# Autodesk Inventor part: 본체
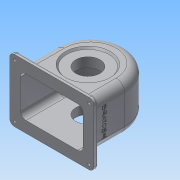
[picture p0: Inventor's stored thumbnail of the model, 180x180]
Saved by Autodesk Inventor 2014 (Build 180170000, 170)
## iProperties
Created: 2016-01
Part Number: 본체
Material: 알루미늄 6061
Document SubType Name: Modeling
Designer: user
Density: 2.71 g/cm^3
Appearance: 알루미늄 - 평지
Mass: 757.291 g
Surface Area: 1005.83 cm^2
Volume: 279.443 cm^3
Author: user
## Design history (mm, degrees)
sketch "스케치3"
  geometry: L1 (-57, -64)-(-57, 0); L2 (57, 0)-(57, -64); L3 (-57, -64)-(57, -64); A1 r 57 centre (0, 0) between (57, 0) and (-57, 0); 2 further points
  constraints: 6 end point, 3 point on circle, 2 tangent, 1 centre point, 1 coincident, 1 horizontal alignment, 1 parallel, 1 perpendicular, 1 vertical
  dimensions: "d6" = 64 distance of L1.start L1.end; "d7" = 121 vertical distance of L2.end point (0, 57)
extrude "돌출2" new body sketch "스케치3" distance "d8" = 77; taper "d9" = 0 deg
feature "쉘1" dims "d10" = 5
fillet "모깎기1" dims "d11" = 9
fillet "모깎기2" dims "d12" = 14
sketch "스케치4"
  geometry: L1 (100, 14)-(100, 63) reference; L2 (0, 77)-(86, 77) reference; L3 (-14, 14)-(-14, 63) reference; L4 (86, 0)-(0, 0) reference; L5 (-27, 90.5)-(113, 90.5); L6 (113, 90.5)-(113, -13.5); L7 (113, -13.5)-(-27, -13.5); L8 (-27, -13.5)-(-27, 90.5); A1 r 14 centre (86, 14) between (86, 0) and (100, 14) reference; A2 r 14 centre (86, 63) between (100, 63) and (86, 77) reference; A3 r 14 centre (0, 63) between (0, 77) and (-14, 63) reference; A4 r 14 centre (0, 14) between (-14, 14) and (0, 0) reference; 5 further points
  constraints: 8 end point, 4 midpoint, 2 parallel, 1 horizontal, 1 horizontal alignment, 1 perpendicular, 1 vertical alignment
  dimensions: "d13" = 104 distance of L7.end L5.start; "d14" = 140 distance of L5.start L5.end
extrude "돌출3" join sketch "스케치4" distance "d15" = 7; taper "d16" = 0 deg
sketch "스케치5"
  geometry: L1 (0, 63)-(0, 77) reference; L2 (0, 77)-(0, 77) reference; L3 (0, 63)-(0, 77) reference; L4 (0, 63)-(0, 63) reference; L5 (-57, 77)-(0, 77) reference; L6 (43, 72)-(0, 72) reference; L7 (35.747, 72)-(24, 58); L8 (24, 58)-(-4, 58); L9 (-4, 58)-(-4, 77); L10 (-64, -13.5)-(-64, 90.5) reference; L11 (0, 77)-(43, 77) reference; L12 (35.747, 72)-(-4, 72); 1 further point
  constraints: 8 end point, 2 parallel, 2 point on line, 1 horizontal alignment, 1 vertical
  dimensions: "d17" = 60 distance from line of L10 L9.end; "d18" = 50 deg angle of L8 L7; "d19" = 56 diameter of L7.end L9; "d20" = 19 distance between parallel lines of L8 L11
revolve "회전1" sketch "스케치5" stored, may be unused: angle "d21" = 90 deg
sketch "스케치6"
  geometry: L1 (0, 0)-(-57, 0) reference; L2 (-32, 58)-(24, 58) reference; L3 (43, 0)-(0, 0) reference; L4 (-4, -10)-(-4, 5); L5 (-64, -13.5)-(-64, 90.5) reference; L6 (-64, 5)-(0, 5) reference; L7 (-4, -10)-(27, -10); L8 (27, -10)-(27, 5); L9 (27, 5)-(-4, 5); 1 further point
  constraints: 8 end point, 2 parallel, 2 perpendicular, 1 horizontal alignment, 1 midpoint
  dimensions: "d69" = 60 distance between parallel lines of L5 L4; "d70" = 10 vertical distance of L3.start L4.start; "d71" = 62 diameter of L7.end L4
node "작업 평면2"
  node "작업 평면1"
sketch "스케치7"
  geometry: L1 (43, 0)-(-43, 0) reference; L2 (-57, 14)-(-57, 63) reference; C1 r 6 at (0, 38.5); 2 further points
  constraints: 1 centre point, 1 horizontal alignment, 1 midpoint, 1 vertical alignment
  dimensions: "d29" = 12 diameter of C1
extrude "돌출4" join sketch "스케치7" stored distance "d30" = 7; taper "d31" = 0 deg
fillet "모깎기3" dims "d32" = 3
hole "구멍1" diameter "d35" = 4.459; stored, may be unused: countersink angle "d39" = 90 deg, drill point angle "d41" = 0 deg; dims "d33" = 10, "d34" = 10, "d36" = 20, "d37" = 4, "d38" = 2, "d40" = 8
fillet "모깎기5" dims "d43" = 1
fillet "모깎기6" dims "d44" = 8
fillet "모깎기7" dims "d45" = 3
sketch "스케치9"
  geometry: C1 r 2.5 at (-19, -82.5); A1 r 5 centre (-19, -82.5) between (-24, -82.5) and (-19, -87.5) reference; 1 further point
  constraints: 1 centre point, 1 coincident
  dimensions: "d59" = 5 diameter of C1
extrude "돌출5" cut sketch "스케치9" stored distance "d60" = 7; taper "d61" = 0 deg
sketch "스케치10"
  geometry: C1 r 2.5 at (-19, 5.5); C2 r 2.5 at (105, 5.5); C3 r 2.5 at (105, -82.5); A1 r 5 centre (105, -82.5) between (105, -87.5) and (110, -82.5) reference; A2 r 5 centre (105, 5.5) between (110, 5.5) and (105, 10.5) reference; A3 r 5 centre (-19, 5.5) between (-19, 10.5) and (-24, 5.5) reference; 1 further point
  constraints: 3 centre point, 3 coincident, 2 equal radius
  dimensions: "d62" = 5 diameter of C1
extrude "돌출6" cut sketch "스케치10" stored distance "d63" = 7; taper "d64" = 0 deg
revolve "회전4" stored, may be unused: angle "d72" = 90 deg
hole "구멍3" diameter "d75" = 40; stored, may be unused: countersink angle "d79" = 90 deg, drill point angle "d81" = 0 deg; dims "d73" = 10, "d74" = 10, "d76" = 40, "d77" = 4, "d78" = 2, "d80" = 17
chamfer "모따기2" distance "d92" = 1; stored, may be unused: second distance "d93" = 2, angle "d94" = 45 deg
fillet "모깎기11" dims "d95" = 3
node "작업 평면3"
sketch "스케치12"
  geometry: C1 r 31 at (0, 0) reference; 2 further points
  constraints: 1 vertical alignment
  dimensions: "d107" = 24 distance of C1.centre point (0, 24)
hole "구멍6" sketch "스케치12" at (0, 24) diameter "d108" = 2.459; stored, may be unused: countersink angle "d112" = 90 deg, drill point angle "d114" = 118 deg; dims "d109" = 6, "d110" = 4, "d111" = 2, "d113" = 8
sketch "스케치13"
  geometry: L1 (-14, 0)-(-14, -56) reference; L2 (-19.5, -64)-(-27.5, -64) reference; 2 further points
  constraints: 1 other
  dimensions: "d118" = 38.5 distance from line of point (24.5, -34) L1; "d119" = 30 distance from line of point (24.5, -34) L2
feature "엠보싱1" sketch "스케치13" dims "d6" = 64, "d7" = 121, "d14" = 140, "d120" = 0.5, "d121" = 0
sketch "스케치14"
  geometry: L1 (-32, 58)-(24, 58) reference; L2 (35.747, 72)-(24, 58) reference; L3 (-4, 58)-(-4, 77); L4 (-64, 80)-(-64, 85) reference; L5 (0, 77)-(43, 77) reference; L6 (-4, 77)-(33.416, 77); L7 (33.416, 77)-(30.899, 74); L8 (30.899, 74)-(-4, 74); 1 further point
  constraints: 8 end point, 2 horizontal alignment, 2 perpendicular, 2 point on line, 1 parallel
  dimensions: "d122" = 60 distance between parallel lines of L4 L3; "d124" = 3 distance between parallel lines of L6 L8; "d125" = 5 distance between parallel lines of L2 L7
revolve "회전5" sketch "스케치14" stored, may be unused: angle "d126" = 90 deg
hole "구멍7" diameter "d129" = 40; stored, may be unused: countersink angle "d133" = 90 deg, drill point angle "d135" = 0 deg; dims "d127" = 10, "d128" = 10, "d130" = 6, "d131" = 4, "d132" = 2, "d134" = 20
node "솔리드2"
pattern_circular "원형 패턴2" dims angle "d116" = 360 deg
node "투영된 루프1"
other parameters: "d27" = 6
